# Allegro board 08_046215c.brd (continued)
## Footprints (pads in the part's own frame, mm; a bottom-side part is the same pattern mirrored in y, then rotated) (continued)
CNSMAL562W375H166
  rect 1.702x0.635 smd: 1(1.079,0)
  rect 5.08x2.54 smd: 2(-0.178,4.255) 3(-0.178,4.255) 4(-0.178,-4.255) 5(-0.178,-4.255)
CNTE2041517-1
  round 1.016 hole 0.711: 1(0,0) 2(1,0.8) 3(0,1.6) 4(1,2.4) 5(0,3.2)
  oval 1.219x2.413 hole 0.711x1.905: G1(-1.25,-0.3) G2(2.25,1.6)
  oval 1.219x2.616 hole 0.711x2.108: G3(-1.25,4)
DFN8_2X2_PAD1_5X1
  oval 0.305x0.61 smd: 1(-0.75,-1.05) 2(-0.25,-1.05) 3(0.25,-1.05) 4(0.75,-1.05) 5(0.75,1.05) 6(0.25,1.05) 7(-0.25,1.05) 8(-0.75,1.05)
  rect 1.499x0.991 smd: PAD(0,0)
DFN8_3X3_PAD2_38X1_64
  oval 0.305x0.838 smd: 1(-0.75,-1.45) 2(-0.25,-1.45) 3(0.25,-1.45) 4(0.75,-1.45) 5(0.75,1.45) 6(0.25,1.45) 7(-0.25,1.45) 8(-0.75,1.45)
  rect 2.388x1.651 smd: PAD(0,0)
DFN8_3X3_PAD2_44X1_6_A
  oval 0.305x0.838 smd: 1(-0.75,-1.45) 2(-0.25,-1.45) 3(0.25,-1.45) 4(0.75,-1.45) 5(0.75,1.45) 6(0.25,1.45) 7(-0.25,1.45) 8(-0.75,1.45)
  rect 2.438x1.6 smd: PAD(0,0)
DQFN16_3_5X2_5_PAD2_15X1_15
  oval 0.889x0.229 smd: 1(-1.795,-0.25) 8(1.795,-0.25) 9(1.795,0.25) 16(-1.795,0.25)
  oval 0.229x0.889 smd: 2(-1.25,-1.294) 3(-0.75,-1.294) 4(-0.25,-1.294) 5(0.25,-1.294) 6(0.75,-1.294) 7(1.25,-1.294) 10(1.25,1.294) 11(0.75,1.294) 12(0.25,1.294) 13(-0.25,1.294) 14(-0.75,1.294) 15(-1.25,1.294)
  rect 1.905x0.991 smd: PAD(0,0)
FLSML476W358H146
  rect 3.81x2.489 smd: 1(-6.845,2.1) 2(6.845,2.1) 3(-6.845,-2.1) 4(6.845,-2.1)
  rect 7.899x2.311 smd: 5(1,-5.094)
  rect 3.404x2.311 smd: 6(3.25,5.094)
HMC849LP4CE
  rect 0.33x0.889 smd: 1(-0.975,-1.841) 2(-0.325,-1.841) 3(0.325,-1.841) 4(0.975,-1.841) 9(0.975,1.841) 10(0.325,1.841) 11(-0.325,1.841) 12(-0.975,1.841)
  rect 0.889x0.33 smd: 5(1.841,-0.975) 6(1.841,-0.325) 7(1.841,0.325) 8(1.841,0.975) 13(-1.841,0.975) 14(-1.841,0.325) 15(-1.841,-0.325) 16(-1.841,-0.975)
  rect 2.388x2.388 smd: PAD(0,0)
L0302CS
  rect 0.254x0.533 smd: 1(-0.305,0) 2(0.305,0)
L0402
  rect 0.889x0.813 smd: 1(-0.635,0) 2(0.635,0)
L0402-2
  rect 0.381x0.66 smd: 1(-0.419,0) 2(0.419,0)
L0603
  rect 0.889x0.813 smd: 1(-0.737,0) 2(0.737,0)
L0603H28
  rect 1.041x0.991 smd: 1(-0.75,0) 2(0.75,0)
L1210
  rect 1.27x1.778 smd: 1(-1.397,0) 2(1.397,0)
LED0603
  rect 0.965x0.762 smd: A(0.8,0) C(-0.8,0)
LED0603H12
  rect 0.787x0.787 smd: A(0.744,0) C(-0.744,0)
LED0805
  rect 1.245x1.092 smd: A(1.172,0) C(-1.172,0)
LSML75W79H39
  rect 1.041x2.21 smd: 1(-0.724,0) 2(0.724,0)
LSML133W118H79
  rect 1.016x1.778 smd: 1(-0.889,0) 2(0.889,0)
LSMSQ130H55
  custom 0.311x0.311 smd: 1(-1.562,0) 2(1.562,0)
LSMSQ154H71
  custom 0.362x0.362 smd: 1(-1.847,0) 2(1.847,0)
LSMSQ157H83
  rect 1.473x3.683 smd: 1(-1.232,0) 2(1.232,0)
POWERPAKSC70-6
  rect 0.305x0.33 smd: 1(-0.65,-0.91) 2(0,-0.91) 3(0.65,-0.91) 4(0.65,0.91) 5(0,0.91) 6(-0.65,0.91)
  rect 0.61x0.94 smd: PAD1(-0.465,0) PAD2(0.465,0)
QFN16_3X3_PAD1_5X1_5
  oval 0.305x0.889 smd: 1(-0.75,-1.5) 2(-0.25,-1.5) 3(0.25,-1.5) 4(0.75,-1.5) 9(0.75,1.5) 10(0.25,1.5) 11(-0.25,1.5) 12(-0.75,1.5)
  oval 0.889x0.305 smd: 5(1.5,-0.75) 6(1.5,-0.25) 7(1.5,0.25) 8(1.5,0.75) 13(-1.5,0.75) 14(-1.5,0.25) 15(-1.5,-0.25) 16(-1.5,-0.75)
  rect 1.499x1.499 smd: PAD(0,0)
QFN16_3X3_PAD1_6X1_6
  oval 0.305x0.889 smd: 1(-0.75,-1.5) 2(-0.25,-1.5) 3(0.25,-1.5) 4(0.75,-1.5) 9(0.75,1.5) 10(0.25,1.5) 11(-0.25,1.5) 12(-0.75,1.5)
  oval 0.889x0.305 smd: 5(1.5,-0.75) 6(1.5,-0.25) 7(1.5,0.25) 8(1.5,0.75) 13(-1.5,0.75) 14(-1.5,0.25) 15(-1.5,-0.25) 16(-1.5,-0.75)
  rect 1.6x1.6 smd: PAD(0,0)
QFN24_4X4_PAD2_5X2_5
  oval 0.305x0.991 smd: 1(-1.25,-2) 2(-0.75,-2) 3(-0.25,-2) 4(0.25,-2) 5(0.75,-2) 6(1.25,-2) 13(1.25,2) 14(0.75,2) 15(0.25,2) 16(-0.25,2) 17(-0.75,2) 18(-1.25,2)
  oval 0.991x0.305 smd: 7(2,-1.25) 8(2,-0.75) 9(2,-0.25) 10(2,0.25) 11(2,0.75) 12(2,1.25) 19(-2,1.25) 20(-2,0.75) 21(-2,0.25) 22(-2,-0.25) 23(-2,-0.75) 24(-2,-1.25)
  rect 2.489x2.489 smd: PAD(0,0)
QFN28_6X6_PAD3_7X3_7
  oval 0.305x1.041 smd: 1(-1.95,-2.979) 2(-1.3,-2.979) 3(-0.65,-2.979) 4(0,-2.979) 5(0.65,-2.979) 6(1.3,-2.979) 7(1.95,-2.979) 15(1.95,2.979) 16(1.3,2.979) 17(0.65,2.979) 18(0,2.979) 19(-0.65,2.979) 20(-1.3,2.979) 21(-1.95,2.979)
  oval 1.041x0.305 smd: 8(2.979,-1.95) 9(2.979,-1.3) 10(2.979,-0.65) 11(2.979,0) 12(2.979,0.65) 13(2.979,1.3) 14(2.979,1.95) 22(-2.979,1.95) 23(-2.979,1.3) 24(-2.979,0.65) 25(-2.979,0) 26(-2.979,-0.65) 27(-2.979,-1.3) 28(-2.979,-1.95)
  rect 3.708x3.708 smd: PAD(0,0)
QFN32_5X5_PAD3_6X3_6
  oval 0.305x0.889 smd: 1(-1.75,-2.451) 2(-1.25,-2.451) 3(-0.75,-2.451) 4(-0.25,-2.451) 5(0.25,-2.451) 6(0.75,-2.451) 7(1.25,-2.451) 8(1.75,-2.451) 17(1.75,2.451) 18(1.25,2.451) 19(0.75,2.451) 20(0.25,2.451) 21(-0.25,2.451) 22(-0.75,2.451) 23(-1.25,2.451) 24(-1.75,2.451)
  oval 0.889x0.305 smd: 9(2.451,-1.75) 10(2.451,-1.25) 11(2.451,-0.75) 12(2.451,-0.25) 13(2.451,0.25) 14(2.451,0.75) 15(2.451,1.25) 16(2.451,1.75) 25(-2.451,1.75) 26(-2.451,1.25) 27(-2.451,0.75) 28(-2.451,0.25) 29(-2.451,-0.25) 30(-2.451,-0.75) 31(-2.451,-1.25) 32(-2.451,-1.75)
  rect 3.607x3.607 smd: PAD(0,0)
QFN38_7X5_PAD5_15X3_15
  oval 0.305x0.838 smd: 1(-2.75,-2.45) 2(-2.25,-2.45) 3(-1.75,-2.45) 4(-1.25,-2.45) 5(-0.75,-2.45) 6(-0.25,-2.45) 7(0.25,-2.45) 8(0.75,-2.45) 9(1.25,-2.45) 10(1.75,-2.45) 11(2.25,-2.45) 12(2.75,-2.45) 20(2.75,2.45) 21(2.25,2.45) 22(1.75,2.45) 23(1.25,2.45) 24(0.75,2.45) 25(0.25,2.45) 26(-0.25,2.45) 27(-0.75,2.45) 28(-1.25,2.45) 29(-1.75,2.45) 30(-2.25,2.45) 31(-2.75,2.45)
  oval 0.838x0.305 smd: 13(3.45,-1.5) 14(3.45,-1) 15(3.45,-0.5) 16(3.45,0) 17(3.45,0.5) 18(3.45,1) 19(3.45,1.5) 32(-3.45,1.5) 33(-3.45,1) 34(-3.45,0.5) 35(-3.45,0) 36(-3.45,-0.5) 37(-3.45,-1) 38(-3.45,-1.5)
  rect 5.156x3.15 smd: PAD(0,0)
QFN48_7X7_PAD5_6X5_6
  oval 0.305x0.94 smd: 1(-2.75,-3.5) 2(-2.25,-3.5) 3(-1.75,-3.5) 4(-1.25,-3.5) 5(-0.75,-3.5) 6(-0.25,-3.5) 7(0.25,-3.5) 8(0.75,-3.5) 9(1.25,-3.5) 10(1.75,-3.5) 11(2.25,-3.5) 12(2.75,-3.5) 25(2.75,3.5) 26(2.25,3.5) 27(1.75,3.5) 28(1.25,3.5) 29(0.75,3.5) 30(0.25,3.5) 31(-0.25,3.5) 32(-0.75,3.5) 33(-1.25,3.5) 34(-1.75,3.5) 35(-2.25,3.5) 36(-2.75,3.5)
  oval 0.94x0.305 smd: 13(3.5,-2.75) 14(3.5,-2.25) 15(3.5,-1.75) 16(3.5,-1.25) 17(3.5,-0.75) 18(3.5,-0.25) 19(3.5,0.25) 20(3.5,0.75) 21(3.5,1.25) 22(3.5,1.75) 23(3.5,2.25) 24(3.5,2.75) 37(-3.5,2.75) 38(-3.5,2.25) 39(-3.5,1.75) 40(-3.5,1.25) 41(-3.5,0.75) 42(-3.5,0.25) 43(-3.5,-0.25) 44(-3.5,-0.75) 45(-3.5,-1.25) 46(-3.5,-1.75) 47(-3.5,-2.25) 48(-3.5,-2.75)
  rect 5.588x5.588 smd: PAD(0,0)
R0201
  rect 0.305x0.406 smd: 1(-0.318,0) 2(0.318,0)
R0402
  rect 0.889x0.813 smd: 1(-0.635,0) 2(0.635,0)
R0603
  rect 1.092x1.194 smd: 1(-0.851,0) 2(0.851,0)
R1206
  rect 1.6x1.6 smd: 1(-1.397,0) 2(1.397,0)
SMB-4
  rect 2.489x2.311 smd: A(2.15,0) C(-2.15,0)
SO8NB-3-PAD
  rect 0.635x1.422 smd: 1(-1.905,-2.819) 2(-0.635,-2.819) 3(0.635,-2.819) 4(1.905,-2.819) 5(1.905,2.819) 6(0.635,2.819) 7(-0.635,2.819) 8(-1.905,2.819)
  rect 2.794x2.413 smd: PAD(0,0)
SOD123-3
  rect 1.194x0.711 smd: A(1.847,0) C(-1.847,0)
TPC65D45
  round 1.651 hole 1.143: 1(0,0)
TPSMC30
  round 0.762 smd: 1(0,0)
TSML150W160H160
  rect 0.762x1.651 smd: 1(-1.27,1.587) 2(0,1.587) 3(1.27,1.587) 4(1.27,-1.587) 5(0,-1.587) 6(-1.27,-1.587)
TSOT-5
  rect 0.508x1.524 smd: 1(-0.95,-1.17) 2(0,-1.17) 3(0.95,-1.17) 4(0.95,1.17) 5(-0.95,1.17)
TSSOP8
  rect 0.33x1.651 smd: 1(-0.975,-2.92) 2(-0.325,-2.92) 3(0.325,-2.92) 4(0.975,-2.92) 5(0.975,2.92) 6(0.325,2.92) 7(-0.325,2.92) 8(-0.975,2.92)
unnamed#2
  round 3.175 hole 2.667: 1(0,0)
YSML276W197H63
  rect 1.956x1.778 smd: 1(-2.54,-1.83) 2(0,-1.83) 3(2.54,-1.83) 4(2.54,1.83) 5(0,1.83) 6(-2.54,1.83)

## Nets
GND: C2.2(N2) C3.2(N2) C6.2(N2) C7.2(N2) C9.2(N2) C12.2(N2) C15.2(N2) C16.1 C17.1 C19.2(N2) C20.2(N2) C21.2(N2) C22.2(N2) C23.2(N2) C24.2(N2) C25.2(N2) C26.2(N2) C27.2(N2) C28.2(N2) C29.2(N2) C30.2(N2) C31.2(N2) C37.2(N2) C40.2(N2) C41.1 C42.1 C43.2(N2) C44.1 C45.1 C46.1 C47.1 C48.1 C49.1 C50.2(N2) C51.2(N2) C52.2(N2) C53.2(N2) C54.2(N2) C55.2(N2) C56.2(N2) C57.2(N2) C58.2(N2) C59.2(N2) C60.2(N2) C61.1 C63.1 C64.2(N2) C65.1 C66.1 C67.2(N2) C69.1 C71.2(N2) C72.2(N2) C76.2(N2) C77.2(N2) C310.1 C311.1 C312.1 C313.1 C314.2(N2) C315.1 C316.2(N2) C317.1 C323.1 C325.1 C326.2(N2) C327.2(N2) C328.2(N2) C330.2(N2) C331.2(N2) C338.1 C339.2(N2) C410.1 C411.1 C419.1 C420.1 C424.1 C426.2(N2) C427.1 C429.1 C430.1 C432.1 C433.2(N2) C435.2(N2) C436.2(N2) C437.2(N2) C443.1 C444.1 C446.1 C510.1 C513.1 C514.2(N2) C515.2(N2) C516.2(N2) C518.1 C522.1 C525.2(N2) C532.1 C535.1 C538.2(N2) C539.2(N2) C541.1 C544.2(N2) C545.2(N2) C546.1 C548.N(N2) C550.2(N2) C554.2(N2) C558.2(N2) C564.N(N2) C566.P C567.2(N2) C612.2(N2) C614.2(N2) C616.2(N2) C617.2(N2) C618.2(N2) C619.2(N2) C620.2(N2) C622.2(N2) C623.2(N2) C626.2(N2) C628.2(N2) C631.2(N2) C636.2(N2) C637.2(N2) C643.2(N2) C645.1 C648.2(N2) C649.1 C651.1 C654.2(N2) C655.2(N2) C656.1 C657.1 C658.1 C659.1 C660.1 C661.1 C662.1 C663.1 C664.1 C665.1 C666.1 C667.1 C668.1 C669.1 C670.1 C818.1 D1.A(P) FL1.3(PSG) FL1.4 FL1.5 FL1.6 J31.2 J31.3 J31.4 J31.5(SH4) J61.2 J61.3(SH2) J62.2 J62.3(SH2) L3.2(N2) L4.2(N2) L45.1 P1.A1 P1.A4 P1.A5 P1.A8 P1.A9 P1.A12 P1.A13 P1.A16 P1.A17 P1.A20 P1.A21 P1.A24 P1.A25 P1.A28 P1.A29 P1.A32 P1.A33 P1.A36 P1.A37 P1.A40 P1.B2 P1.B3 P1.B6 P1.B7 P1.B10 P1.B11 P1.B14 P1.B15 P1.B18 P1.B19 P1.B22 P1.B23 P1.B26 P1.B27 P1.B30 P1.B31 P1.B34 P1.B35 P1.B38 P1.B39 P1.C1 P1.C4 P1.C5 P1.C8 P1.C9 P1.C12 P1.C13 P1.C16 P1.C17 P1.C20 P1.C21 P1.C24 P1.C25 P1.C28 P1.C29 P1.C32 P1.C33 P1.C36 P1.C38 P1.C40 P1.D2 P1.D3 P1.D6 P1.D7 P1.D10 P1.D16 P1.D19 P1.D22 P1.D25 P1.D28 P1.D37 P1.D39 P1.E1 P1.E4 P1.E5 P1.E8 P1.E11 P1.E14 P1.E17 P1.E20 P1.E23 P1.E26 P1.E29 P1.E32 P1.E35 P1.E38 P1.E40 P1.F2 P1.F3 P1.F6 P1.F9 P1.F12 P1.F15 P1.F18 P1.F21 P1.F24 P1.F27 P1.F30 P1.F33 P1.F36 P1.F39 P1.G1 P1.G4 P1.G5 P1.G8 P1.G11 P1.G14 P1.G17 P1.G20 P1.G23 P1.G26 P1.G29 P1.G32 P1.G35 P1.G38 P1.G40 P1.H2 P1.H3 P1.H6 P1.H9 P1.H12 P1.H15 P1.H18 P1.H21 P1.H24 P1.H27 P1.H30 P1.H33 P1.H36 P1.H39 P1.J1 P1.J4 P1.J5 P1.J8 P1.J11 P1.J14 P1.J17 P1.J20 P1.J23 P1.J26 P1.J29 P1.J32 P1.J35 P1.J38 P1.J40 P1.K2 P1.K3 P1.K6 P1.K9 P1.K12 P1.K15 P1.K18 P1.K21 P1.K24 P1.K27 P1.K30 P1.K33 P1.K36 P1.K39 Q1.1 Q1.4(S2) Q2.1 Q2.4(S2) Q3.1 Q3.4(S2) Q4.1 Q4.4(S2) R1.2(N2) R3.2(N2) R8.1 R9.2(N2) R15.1 R17.2(N2) R27.2(N2) R41.1 R42.2(N2) R60.2(N2) R61.1 R67.2(N2) R69.1 R76.2(N2) R78.2(N2) R80.2(N2) R88.1 R310.1 R311.1 R328.1 R330.2(N2) R413.2(N2) R417.1 R423.2(N2) R424.2(N2) R429.1 R436.2(N2) R617.2(N2) R618.2(N2) R621.1 R623.2(N2) T33.2 TP42.1(N1) TP64.1(N1) U1.A13 U1.A14 U1.B1 U1.B2 U1.C2 U1.D2 U1.D3 U1.D13 U1.D14 U1.D15 U1.E1 U1.E2 U1.E3 U1.E13 U1.E14 U1.F6 U1.F7 U1.F8 U1.F9 U1.F10 U1.G2 U1.G3 U1.G8 U1.G13 U1.G14 U1.H1 U1.H3 U1.H6 U1.H7 U1.H8 U1.H9 U1.H10 U1.H13 U1.H15 U1.J6 U1.J7 U1.J8 U1.J9 U1.J10 U1.L1 U1.L2 U1.L14 U1.L15 U1.N6 U1.N7 U1.N10 U1.P1 U1.P15 U1.R2 U1.R5 U1.R8 U1.R11 U1.R14 U2.7 U2.PAD U3.7 U3.PAD U4.2 U5.5 U5.10 U5.11 U5.PAD U6.4 U6.PAD U7.PAD U8.9 U8.12 U8.13 U8.14 U8.24 U8.30 U8.PAD U9.8 U9.PAD U10.2 U10.3 U10.10 U10.11 U10.30 U10.PAD U11.10 U11.PAD U12.6 U13.4 U13.PAD U14.4 U14.PAD U15.8 U15.9 U15.13 U15.18 U15.21 U15.31 U15.PAD U16.7 U16.14 U16.PAD U17.4 U17.PAD U18.4 U18.PAD U19.4 U19.PAD U20.5 U20.16 U20.PAD U21.8 U21.10 U21.PAD U22.8 U22.PAD U23.4 U23.7(WC_N) XC4.N(N2) XC5.2(N2) XC6.2(N2) XC12.1 XP1.6(N6) XP2.5 XP2.G1 XP2.G2 XP2.G3(N8) Y61.3
SVDD12: C20.1 C26.1 C31.1 C37.1 C43.1 C52.1 C532.2(N2) C535.2(N2) C541.2(N2) C546.2(N2) C554.1 C567.1 U1.J2 U1.J14 U1.K2 U1.K14 U1.L3 U1.L13 U1.M2 U1.M3 U1.M13(VTT_1P2_2) U1.M14 U1.N2 U1.N8 U1.N9 U1.N14 U1.P3 U1.P4 U1.P6 U1.P7 U1.P9 U1.P10 U1.P12 U1.P13 U1.R1 U1.R15 U3.9 U3.10 U3.11 U3.12 U3.13
VCC: C58.1 R29.1 R30.1 R40.1 R50.2(N2) R51.2(N2) R52.2(N2) R53.1 R55.2(N2) R56.2(N2) R57.2(N2) R58.2(N2) R63.1 R68.1 R77.1 R79.1 R327.1 U8.22 U8.25(VSEL)
VDDA12: C50.1 C558.1 E9.1 U1.B13 U1.B14 U2.9 U2.10 U2.11 U2.12 U2.13
VDDA25: C1.2(N2) C5.2(N2) C32.2 C32.4 C32.6 C32.8(N8) C33.2 C33.4 C33.6 C33.8(N8) C35.2(N2) C36.2(N2) C513.2(N2) C531.1 C534.1 C537.1 C543.1 C549.1 E6.2(N2) E7.1 R33.1 R34.2(N2) R59.1 T1.3 U1.A2 U1.A5 U1.A6 U1.A9 U1.A10 U1.B3 U1.B6 U1.B7 U1.B8 U1.B9 U1.B12 U1.C4 U1.C7 U1.C8 U1.C11 U1.C15 U13.2
VDDA25_EN: Q4.3 Q4.PAD2 R52.1 U13.7
VDDC12: C526.P C533.1 C536.1 C539.1 C545.1 E9.2(N2) U1.E15 U1.F1 U1.F2 U1.F3 U1.F13 U1.F14 U1.F15
VIN_12V: C41.2(N2) C42.2(N2) C44.2(N2) C45.2(N2) C433.1 DS2.A(P) FL1.2 R54.1 R428.1 U10.6 U10.7 U10.22 U10.23 U10.24 U10.36 U10.37 U10.38 U11.12 U11.13
3P3VAUX: C818.2(N2) P1.D32 U23.8
73_SYNC: R429.2(N2) U11.4
73_VREF: C429.2(N2) R434.2(N2) U11.9
73_VREG: C430.2(N2) R425.1 U11.11(VREG)
AD9508_VDD: C323.2(N2) C327.1 C328.1 C330.1 C331.1 E32.1 R35.2(N2) R36.2(N2) R38.2(N2) R39.2(N2) R312.1 R313.1 U7.6 U7.13(VDD2)
ADCLK914OUT: C39.1 R625.1 U16.11
ADCLK914VCC: C654.1 C655.1 E68.2(N2) R622.1 R625.2(N2) U16.8 U16.13
ADF4355_VDD_3V3: C614.1 C616.1 C669.2(N2) JP1.2(S2) R611.2(N2) R619.2(N2) U15.5 U15.16 U15.27 U18.2
ADF4355_VRF_3V3: C623.1 C626.1 E5.1 E67.2(N2) L61.1 L62.2(N2) U15.10
ADF4355_VVCO_5V: C618.1 C619.1 C636.1 C643.1 C668.2(N2) U15.6 U15.17(VVCO) U15.19 U17.2
ADF4355OUTA: C632.2(N2) U16.2
ADF4355OUTAB: C633.2(N2) U16.1
ADF4355OUTB: C638.2(N2) U9.7
ADF4355OUTBB: C639.2(N2) U9.5
ADP5054_1V2: C2.1 C3.1 C16.2(N2) C17.2(N2) C18.1 C525.1 C538.1 C544.1 C550.1 C564.P E8.2(N2) R16.2(N2) U1.G6 U1.G7 U1.G9 U1.G10 U1.K6 U1.K7 U1.K8 U1.K9 U1.K10
ADP5054_1V5: C19.1 C28.1 C29.1 E1.2(N2) R2.2(N2) R24.1 R25.1 U2.1 U2.2 U2.3 U2.4 U2.16 U3.1 U3.2 U3.3 U3.4
ADP5054_3V8: C6.1 C56.1 C420.2(N2) C516.1 E2.2(N2) L1.1 L5.1 R63.2(N2) U4.1 U13.8 U14.8
ADP5054_5V5: C419.2(N2) E3.2(N2) E31.1 L2.1
ADP5073_2V2: C446.2(N2) E49.1 R443.1
CLK_N: C349.2(N2) U1.D1
CLK_P: C348.2(N2) U1.C1
CPOUT: C61.2(N2) C62.1 R62.1 U15.7
CS1: P2.2 R19.1 U20.20 U21.14
CS2: R38.1 R316.1 U20.10 U22.11
CS3: R615.1 U20.4 U22.13
DAC_CSB: R19.2(N2) U1.G15
DAC_SCLK: R23.2(N2) U1.J13
DAC_SDIO: R22.2(N2) U1.K13
DAC_SDO: R20.2(N2) U1.H14
DAC_TXEN_0: R8.2(N2) R18.2(N2) U1.H2
DIV2IN: C341.2(N2) U7.21
DIV2INB: C340.2(N2) U7.22
DL1: Q1.2 U10.31
DL2: Q1.5 U10.29
EN: Q3.3 Q3.PAD2 R51.1 U4.3
FMC_CS1: P1.H11 U21.3
FMC_CS2: P1.D11 U22.6
FMC_CS3: P1.D14 U22.4
FMC_HMC849VCTL: P1.D15 U22.3
FMC_MISO: P1.H10 U21.5
FMC_MOSI: P1.G10 U21.4
FMC_SCK: P1.G9 U21.6
FMC_SCL: P1.C30 U23.6
FMC_SDA: P1.C31 U23.5
FMC_SPI_EN: P1.D12 R72.2(N2) R73.2(N2) U20.6 U21.9 U22.9
FMC_TXEN_0: P1.H13 U22.5
FMCA_VCC_12P0V: C548.P D1.C FL1.1 P1.C35 P1.C37 TP41.1(N1)
GA0: P1.C34 U23.1
GA1: P1.D35 U23.2
GBTCLK0_M2C_N: C333.2(N2) P1.D5
GBTCLK0_M2C_P: C334.2(N2) P1.D4
HMC365_VDD: C317.2(N2) C338.2(N2) C339.1 U6.2 U9.4(VCC)
HMC365OUT: C341.1 R37.2(N2) R329.2(N2) U9.3
HMC365OUTB: C340.1 R37.1 R328.2(N2) U9.1
HMC849_VDD: C311.2(N2) C314.1 C316.1 E66.2(N2) U5.1(VDD)
HMC849VCTL: R31.2(N2) U20.9 U22.14
IRQB: CR5.C TP21.1(N1) U1.G1
LTC2928_ON: R70.2(N2) R416.1 U10.17
LTC2928_ON_A: R71.2(N2) U11.3
MISO: R20.1 U20.19 U21.12
MOSI: P2.1 R22.1 R36.1 R315.1 R614.1 U20.18 U21.13
OUT_N: E6.1 R33.2(N2) T1.6 U1.A7
OUT_P: E7.2(N2) R34.1 T1.4 U1.A8
PG_C2M: P1.D1 R47.2(N2) R410.2(N2) R411.2(N2) R412.2(N2) R428.2(N2) R436.1 U11.6
PGC: U20.24 XP1.3
PWRGD: DS1.C U8.19 U20.28
REF: R75.2(N2) U8.5
REF_4355_N: C610.1 Y61.5
REF_4355_P: C611.1 R65.1 Y61.4
SA_GND: C1.1 C5.1 C32.1 C32.3 C32.5 C32.7 C33.1 C33.3 C33.5 C33.7 C35.1 C36.1 J32.2 J32.3 J32.4 J32.5(SH4) L3.1 L4.1
SCK: P2.3(N3) R23.1 R35.1 R314.1 R613.1 U20.15 U21.11
SERDIN0_N: C816.1 U1.K15
SERDIN0_P: C815.1 U1.J15
SERDIN1_N: C82.1 U1.N15
SERDIN1_P: C81.1 U1.M15
SERDIN2_N: C84.1 U1.R12
SERDIN2_P: C83.1 U1.R13
SERDIN3_N: C86.1 U1.R9
SERDIN3_P: C85.1 U1.R10
SERDIN4_N: C811.1 U1.R7
SERDIN4_P: C812.1 U1.R6
SERDIN5_N: C87.1 U1.R4
SERDIN5_P: C88.1 U1.R3
SERDIN6_N: C813.1 U1.N1
SERDIN6_P: C814.1 U1.M1
SERDIN7_N: C89.1 U1.K1
SERDIN7_P: C810.1 U1.J1
SLEW: R425.2(N2) U11.2
SPI33: C59.1 E4.2(N2) R5.1 R6.1 U1.K3
SUPPLY33: C9.1 C76.1 C77.1 E4.1 E32.2(N2) R28.2(N2) R66.1 U4.5(VOUT) U20.11(VUSB) U20.17 U21.16(VCCB) U22.16(VCCB) XC4.P XC5.1 XC6.1 XP1.2 XR2.1 XR6.1
SVPLL12_EN: R338.2(N2) U3.16
SVSYN33_EN: R339.2(N2) U14.7
SVSYNC33: C522.2(N2) U1.P2 U1.P14 U14.2
SW1: C10.2(N2) L6.1 Q1.6 Q1.PAD1 U10.33 U10.34 U10.35
SW2: C412.2(N2) L7.1 Q1.3 Q1.PAD2 U10.25 U10.26 U10.27
SWITCH2BALUN: C38.1 R332.1
SYNC_N: JP34.1 R26.1 SYNCN.1(N1) U1.N11
SYNC_P: JP33.1 R26.2(N2) SYNCP.1(N1) U1.N12
SYSREF2_N: C344.2(N2) JP32.1
SYSREF2_P: C345.2(N2) JP31.1
SYSREF_N: C346.2(N2) R32.1 SYSRFN.1(N1) U1.N5
SYSREF_P: C347.2(N2) R32.2(N2) SYSRFP.1(N1) U1.N4
TOAD9508: R329.1 R629.2(N2)
TXEN_0: R18.1 U20.8 U22.12
UNNAMED_2_AD9162V4_I56_ISET: R7.1 U1.A15
UNNAMED_2_AD9162V4_I56_PLLLDOBY: R21.2(N2) U1.P8
UNNAMED_2_AD9162V4_I56_RESETN: R4.1 U1.J3
UNNAMED_2_AD9162V4_I56_VBGNEG: C8.1 U1.C12
UNNAMED_2_AD9162V4_I56_VREF: C23.1 U1.B15
UNNAMED_2_CAP_I33_N1: C21.1 R21.1
UNNAMED_2_CAP_I39_N1: C7.1 R3.1 R4.2(N2) R5.2(N2)
UNNAMED_2_DIOLED_I48_P: CR5.A(P) R6.2(N2)
UNNAMED_3_AD9508_I1155_EXTCAP1: C325.2(N2) U7.5
UNNAMED_3_AD9508_I1155_EXTCAP2: C326.1 U7.14
UNNAMED_3_AD9508_I1155_INSEL: R39.1 R330.1 U7.23
UNNAMED_3_AD9508_I1155_OUT0: C333.1 U7.2
UNNAMED_3_AD9508_I1155_OUT0B: C334.1 U7.3
UNNAMED_3_AD9508_I1155_OUT2: C344.1 U7.11
UNNAMED_3_AD9508_I1155_OUT2B: C345.1 U7.12
UNNAMED_3_AD9508_I1155_OUT3: C346.1 U7.16
UNNAMED_3_AD9508_I1155_OUT3B: C347.1 U7.17
UNNAMED_3_AD9508_I1155_RESETB: R311.2(N2) R312.2(N2) U7.18
UNNAMED_3_AD9508_I1155_S0: R314.2(N2) U7.19
UNNAMED_3_AD9508_I1155_S1: R315.2(N2) U7.24
UNNAMED_3_AD9508_I1155_S2: R316.2(N2) U7.1
UNNAMED_3_AD9508_I1155_SYNCB: R310.2(N2) R313.2(N2) U7.20
UNNAMED_3_ADM7150_I1277_BYP: C312.2(N2) U6.3
UNNAMED_3_ADM7150_I1277_EN: C313.2(N2) E31.2(N2) U6.7 U6.8
UNNAMED_3_ADM7150_I1277_REF: C315.2(N2) U6.5 U6.6
UNNAMED_3_ADM7150_I1277_VREG: C310.2(N2) U6.1(VREG)
UNNAMED_3_CAP_I1148_N2: C39.2(N2) U5.12
UNNAMED_3_CAP_I1149_N2: C34.2(N2) U5.9
UNNAMED_3_CAP_I1150_N2: C38.2(N2) U5.3
UNNAMED_3_CAP_I1305_N1: C349.1 T33.6(SEC_DOT)
UNNAMED_3_CAP_I1306_N1: C348.1 T33.4
UNNAMED_3_CAP_I1318_N1: C14.1 J32.1
UNNAMED_3_CAP_I1318_N2: C14.2(N2) T1.1 T1.2(NC1)
UNNAMED_3_CNBNC5P_I1037_CNTR: C34.1 J31.1
UNNAMED_3_ICHMC849LP4CE_I1139_V: R31.1 U5.2
UNNAMED_3_RES_I1265_N2: R332.2(N2) T33.3
UNNAMED_4_ADP5054_I1011_BST1: C10.1 U10.32
UNNAMED_4_ADP5054_I1011_BST2: C412.1 U10.28
UNNAMED_4_ADP5054_I1011_BST3: C413.1 U10.1
UNNAMED_4_ADP5054_I1011_BST4: C415.1 U10.12
UNNAMED_4_ADP5054_I1011_CFG12: R41.2(N2) R48.1 U10.18
UNNAMED_4_ADP5054_I1011_CFG34: R42.1 R49.1 U10.13
UNNAMED_4_ADP5054_I1011_COMP1: R44.2(N2) U10.40
UNNAMED_4_ADP5054_I1011_COMP2: R45.2(N2) U10.20
UNNAMED_4_ADP5054_I1011_COMP3: R46.2(N2) U10.47
UNNAMED_4_ADP5054_I1011_COMP4: R43.2(N2) U10.15
UNNAMED_4_ADP5054_I1011_EN1: R47.1 U10.39
UNNAMED_4_ADP5054_I1011_EN2: R410.1 U10.21
UNNAMED_4_ADP5054_I1011_EN3: R411.1 U10.48
UNNAMED_4_ADP5054_I1011_EN4: R412.1 U10.14
UNNAMED_4_ADP5054_I1011_FB1: C11.1 R15.2(N2) R16.1 U10.41
UNNAMED_4_ADP5054_I1011_FB2: C13.1 R1.1 R2.1 U10.19
UNNAMED_4_ADP5054_I1011_FB3: R420.2(N2) R424.1 U10.46
UNNAMED_4_ADP5054_I1011_FB4: R419.2(N2) R423.1 U10.16
UNNAMED_4_ADP5054_I1011_RT: R413.1 U10.42
UNNAMED_4_ADP5054_I1011_SW31: C413.2(N2) L44.1 U10.4 U10.5
UNNAMED_4_ADP5054_I1011_SW41: C415.2(N2) L42.1 U10.8 U10.9
UNNAMED_4_ADP5054_I1011_SYNC: R414.2(N2) U10.44
UNNAMED_4_ADP5054_I1011_VDD: C411.2(N2) U10.43
UNNAMED_4_ADP5073_I1002_COMP: C436.1 R437.1 U11.7
UNNAMED_4_ADP5073_I1002_FB: R430.2(N2) R434.1 U11.8
UNNAMED_4_ADP5073_I1002_SW: D42.C L45.2(N2) U11.1
UNNAMED_4_ADP7183_I808_VA: C434.2(N2) C435.1 U12.3
UNNAMED_4_ADP7183_I808_VAFB: C434.1 U12.4
UNNAMED_4_ADP7183_I808_VIN: C426.1 R443.2(N2) U12.8 U12.PAD
UNNAMED_4_ADP7183_I808_VREG: C427.2(N2) U12.7(VREG)
UNNAMED_4_CAP_I904_N2: C424.2(N2) D42.A(P) E49.2(N2) R430.1
UNNAMED_4_CAP_I948_N2: C443.2(N2) E2.1 L44.2(N2) R420.1
UNNAMED_4_CAP_I949_N2: C444.2(N2) E3.1 L42.2(N2) R419.1
UNNAMED_4_CAP_I1000_N1: C437.1 R437.2(N2)
UNNAMED_4_CAP_I1019_N2: C47.2(N2) R44.1
UNNAMED_4_CAP_I1026_N2: C48.2(N2) R45.1
UNNAMED_4_CAP_I1027_N2: C49.2(N2) R46.1
UNNAMED_4_CAP_I1028_N2: C46.2(N2) R43.1
UNNAMED_4_CAP_I1107_N2: C18.2(N2) R17.1
UNNAMED_4_CAP_I1125_N1: C11.2(N2) C12.1 C53.1 E8.1 L6.2(N2)
UNNAMED_4_CAP_I1127_N1: C13.2(N2) C15.1 C54.1 E1.1 L7.2(N2)
UNNAMED_4_DIOLED_I1138_N: DS2.C R417.2(N2)
UNNAMED_5_ADCLK914_I223_Q: C4.1 R622.2(N2) U16.12
UNNAMED_5_ADCLK914_I223_VREF: C649.2(N2) U16.15 U16.16
UNNAMED_5_ADF4355_I299_CE: R611.1 U15.4
UNNAMED_5_ADF4355_I299_CLK: R613.2(N2) U15.1
UNNAMED_5_ADF4355_I299_CREG2: C612.1 C617.1 U15.32
UNNAMED_5_ADF4355_I299_DATA: R614.2(N2) U15.2
UNNAMED_5_ADF4355_I299_LE: R615.2(N2) U15.3
UNNAMED_5_ADF4355_I299_MUXOUT: R620.1 U15.30
UNNAMED_5_ADF4355_I299_REFINA: C611.2(N2) R69.2(N2) R612.1 U15.29
UNNAMED_5_ADF4355_I299_REFINB: C610.2(N2) R612.2(N2) U15.28
UNNAMED_5_ADF4355_I299_RFOUTB: L64.1 R11.2(N2) R13.1 U15.15
UNNAMED_5_ADF4355_I299_RFOUTB_1: L63.2(N2) R11.1 R12.1 U15.14
UNNAMED_5_ADF4355_I299_RSET: R618.1 U15.22
UNNAMED_5_ADF4355_I299_VBIAS: C637.1 C645.2(N2) U15.24
UNNAMED_5_ADF4355_I299_VREF: C648.1 C651.2(N2) U15.23
UNNAMED_5_ADM7150_I186_BYP: C659.2(N2) U17.3
UNNAMED_5_ADM7150_I186_REF: C665.2(N2) U17.5 U17.6
UNNAMED_5_ADM7150_I186_VIN: C662.2(N2) L2.2(N2) U17.7 U17.8
UNNAMED_5_ADM7150_I186_VREG: C656.2(N2) U17.1(VREG)
UNNAMED_5_ADM7154_I181_BYP: C661.2(N2) U19.3
UNNAMED_5_ADM7154_I181_REF: C667.2(N2) U19.5 U19.6
UNNAMED_5_ADM7154_I181_VIN: C664.2(N2) L1.2(N2) U19.7 U19.8
UNNAMED_5_ADM7154_I181_VOUT: C670.2(N2) R626.1 R627.1 R628.1 U19.2
UNNAMED_5_ADM7154_I181_VREG: C658.2(N2) U19.1(VREG)
UNNAMED_5_ADM7154_I297_BYP: C660.2(N2) U18.3
UNNAMED_5_ADM7154_I297_EN: C663.2(N2) L5.2(N2) U18.7 U18.8
UNNAMED_5_ADM7154_I297_REF: C666.2(N2) U18.5 U18.6
UNNAMED_5_ADM7154_I297_VREG: C657.2(N2) U18.1(VREG)
UNNAMED_5_CAP_I32_N2: C66.2(N2) R62.2(N2) R64.1
UNNAMED_5_CAP_I90_N1: C633.1 L62.1 U15.12
UNNAMED_5_CAP_I203_N2: C63.2(N2) C65.2(N2) JP1.1 Y61.6(VDD)
UNNAMED_5_CAP_I269_N1: C620.1 C622.1 U15.25
UNNAMED_5_CAP_I292_N1: C638.1 R12.2(N2) R14.1
UNNAMED_5_CAP_I293_N1: C639.1 R13.2(N2) R14.2(N2)
UNNAMED_5_CAP_I294_N1: C632.1 L61.2(N2) U15.11
UNNAMED_5_CAP_I329_N1: C628.1 C631.1 E5.2(N2) L63.1 L64.2(N2)
UNNAMED_5_CAP_I349_N2: C62.2(N2) R61.2(N2)
UNNAMED_5_CNBNC3P_I279_CNTR: C4.2(N2) J62.1 R623.1
UNNAMED_5_CNBNC3P_I308_CNTR: J61.1 R65.2(N2) R629.1
UNNAMED_5_DIOLED_I73_N: DS61.C R621.2(N2)
UNNAMED_5_DIOLED_I73_P: DS61.A(P) R620.2(N2)
UNNAMED_5_FERRITE_I346_N1: E68.1 R626.2(N2)
UNNAMED_5_FERRITE_I347_N1: E67.1 R628.2(N2)
UNNAMED_5_FERRITE_I348_N1: E66.1 R627.2(N2)
UNNAMED_5_RES_I49_N1: R617.1 R619.1 U15.26
UNNAMED_6_CAP_I116_N2: U20.3 XC12.2(N2)
UNNAMED_6_CN6P_I38_N1: U20.25 XP1.1
UNNAMED_6_CN6P_I38_N5: U20.26 XP1.5 XR2.2(N2)
UNNAMED_6_DIOLED_I258_N: U20.21 XCR1.C
UNNAMED_6_DIOLED_I258_P: XCR1.A(P) XR6.2(N2)
UNNAMED_6_ICPIC18F2XJ50_I109_OS: R28.1 U20.7
UNNAMED_6_ICPIC18F2XJ50_I109_RC: R10.1 U20.14
UNNAMED_7_CAP_I162_N2: C811.2(N2) P1.B32
UNNAMED_7_CAP_I163_N2: C812.2(N2) P1.B33
UNNAMED_7_CAP_I164_N2: C813.2(N2) P1.B36
UNNAMED_7_CAP_I165_N2: C814.2(N2) P1.B37
UNNAMED_7_CAP_I166_N2: C82.2(N2) P1.A23
UNNAMED_7_CAP_I167_N2: C81.2(N2) P1.A22
UNNAMED_7_CAP_I168_N2: C84.2(N2) P1.A27
UNNAMED_7_CAP_I169_N2: C83.2(N2) P1.A26
UNNAMED_7_CAP_I170_N2: C86.2(N2) P1.A31
UNNAMED_7_CAP_I171_N2: C85.2(N2) P1.A30
UNNAMED_7_CAP_I172_N2: C88.2(N2) P1.A35
UNNAMED_7_CAP_I173_N2: C87.2(N2) P1.A34
UNNAMED_7_CAP_I174_N2: C810.2(N2) P1.A39
UNNAMED_7_CAP_I175_N2: C89.2(N2) P1.A38
UNNAMED_7_CAP_I176_N2: C816.2(N2) P1.C3
UNNAMED_7_CAP_I177_N2: C815.2(N2) P1.C2
UNNAMED_7_CN400PAKV2_I143_LA01N: JP34.2(N2) P1.D9
UNNAMED_7_CN400PAKV2_I143_LA01P: JP33.2(N2) P1.D8
UNNAMED_7_CN400PAKV2_I143_TDI: P1.D30 P1.D31
UNNAMED_7_CN400PAKV2_I147_LA02N: JP32.2(N2) P1.H8
UNNAMED_7_CN400PAKV2_I147_LA02P: JP31.2(N2) P1.H7
UNNAMED_7_ICM24CXX_I210_E2: R88.2(N2) U23.3
UNNAMED_9_ADM7154_I249_BYP: C515.1 U14.3
UNNAMED_9_ADM7154_I249_REF: C518.2(N2) U14.5 U14.6
UNNAMED_9_ADM7154_I249_VREG: C514.1 U14.1(VREG)
UNNAMED_9_ADM7154_I278_BYP: C55.1 U13.3
UNNAMED_9_ADM7154_I278_REF: C510.2(N2) U13.5 U13.6
UNNAMED_9_ADM7154_I278_VREG: C51.1 U13.1(VREG)
UNNAMED_9_ADP176X_I287_PG: R24.2(N2) U2.15
UNNAMED_9_ADP176X_I287_REFCAP: C25.1 U2.5
UNNAMED_9_ADP176X_I287_SS: C22.1 U2.14
UNNAMED_9_ADP176X_I287_VREG: C30.1 U2.6(VREG)
UNNAMED_9_ADP176X_I303_PG: R25.2(N2) U3.15
UNNAMED_9_ADP176X_I303_REFCAP: C27.1 U3.5
UNNAMED_9_ADP176X_I303_SS: C24.1 U3.14
UNNAMED_9_ADP176X_I303_VREG: C40.1 U3.6(VREG)
UNNAMED_9_CAPP_I31_N2: C526.N(N2) R27.1
UNNAMED_10_CAP_I3_N1: C64.1 U8.26
UNNAMED_10_CAP_I4_N1: C60.1 U8.27
UNNAMED_10_CAP_I5_N1: C67.1 U8.28
UNNAMED_10_CAP_I7_N1: C57.1 R54.2(N2) U8.23
UNNAMED_10_DIOLED_I29_P: DS1.A(P) R327.2(N2)
UNNAMED_10_LINLTC2928_I1_DONEN: R53.2(N2) U8.18
UNNAMED_10_LINLTC2928_I1_EN1: Q2.2 U8.2
UNNAMED_10_LINLTC2928_I1_EN2: Q3.2 U8.37
UNNAMED_10_LINLTC2928_I1_EN3: Q4.2 U8.31
UNNAMED_10_LINLTC2928_I1_ON: R68.2(N2) R70.1 R71.1 U8.16
UNNAMED_10_LINLTC2928_I1_OVA: R55.1 R76.1 U8.1
UNNAMED_10_LINLTC2928_I1_RT1: R56.1 U8.6
UNNAMED_10_LINLTC2928_I1_RT2: R58.1 U8.7
UNNAMED_10_LINLTC2928_I1_RT3: R57.1 U8.8
UNNAMED_10_LINLTC2928_I1_SQT1: R77.2(N2) R78.1 U8.10
UNNAMED_10_LINLTC2928_I1_SQT2: R79.2(N2) R80.1 U8.11
UNNAMED_10_LINLTC2928_I1_V1: R74.2(N2) R75.1 U8.3
UNNAMED_10_LINLTC2928_I1_V2: R66.2(N2) R67.1 U8.38
UNNAMED_10_LINLTC2928_I1_V3: R59.2(N2) R60.1 U8.32
UNNAMED_10_RES_I26_N1: Q2.3 Q2.PAD2 R50.1 R337.1 R338.1 R339.1
UNNAMED_10_TRANNMOSFET2PAD_I17_: Q4.5 Q4.6 Q4.PAD1 R29.2(N2)
UNNAMED_10_TRANNMOSFET2PAD_I21_: Q3.5 Q3.6 Q3.PAD1 R40.2(N2)
UNNAMED_10_TRANNMOSFET2PAD_I24_: Q2.5 Q2.6 Q2.PAD1 R30.2(N2)
USB_D+: U20.13 XP2.3
USB_D-: U20.12 XP2.2
USB_VCC: R9.1 R10.2(N2) XP2.1
VADJ: C71.1 C72.1 P1.E39 P1.F40 P1.G39 P1.H40 P1.J39 P1.K40 R72.1 R73.1 U21.1 U21.2 U21.7 U21.15 U22.1 U22.2 U22.7 U22.10 U22.15
VNEG12: C8.2(N2) C531.2(N2) C533.2(N2) C534.2(N2) C536.2(N2) C537.2(N2) C543.2(N2) C549.2(N2) C566.N(N2) R7.2(N2) R445.2(N2) TP43.1(N1) U1.A1 U1.A3 U1.A4 U1.A11 U1.A12 U1.B4 U1.B5 U1.B10 U1.B11 U1.C5 U1.C6 U1.C9 U1.C10 U1.C14
VNEG12_EN: R337.2(N2) U12.5
VOUT: C432.2(N2) R74.1 R445.1 U12.1 U12.2
VREG: C410.2(N2) R48.2(N2) R49.2(N2) R414.1 R416.2(N2) U10.45(VREG)
VTUNE: C69.2(N2) R64.2(N2) U15.20

Pads without a net: NOREF#23 1; NOREF#25 1; P1 A2 A3 A6 A7 A10 A11 A14 A15 A18 A19 B1 B4 B5 B8 B9 B12 B13 B16 B17 B20 B21 B24 B25 B28 B29 B40 C6 C7 C10 C11 C14 C15 C18 C19 C22 C23 C26 C27 C39 D13 D17 D18 D20 D21 D23 D24 D26 D27 D29 D33 D34 D36 D38 D40 E2 E3 E6 E7 E9 E10 E12 E13 E15 E16 E18 E19 E21 E22 E24 E25 E27 E28 E30 E31 E33 E34 E36 E37 F1 F4 F5 F7 F8 F10 F11 F13 F14 F16 F17 F19 F20 F22 F23 F25 F26 F28 F29 F31 F32 F34 F35 F37 F38 G2 G3 G6 G7 G12 G13 G15 G16 G18 G19 G21 G22 G24 G25 G27 G28 G30 G31 G33 G34 G36 G37 H1 H4 H5 H14 H16 H17 H19 H20 H22 H23 H25 H26 H28 H29 H31 H32 H34 H35 H37 H38 J2 J3 J6 J7 J9 J10 J12 J13 J15 J16 J18 J19 J21 J22 J24 J25 J27 J28 J30 J31 J33 J34 J36 J37 K1 K4 K5 K7 K8 K10 K11 K13 K14 K16 K17 K19 K20 K22 K23 K25 K26 K28 K29 K31 K32 K34 K35 K37 K38; T33 1 5; U1 P5 P11; U2 8; U3 8; U4 4; U5 4 6 7 8 13 14 15 16; U7 4 7 8 9 10 15; U8 4 15 17 20 21 29 33 34 35 36; U9 2 6; U11 5 14 15 16; U16 3 4 5 6 9 10; U20 1 2 22 23 27; XP1 4; XP2 4; Y61 1 2

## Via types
v1: diameter 0.508, hole 0.254, TOP to BOTTOM, 342 vias
v2: diameter 0.508, hole 0.254, L2_GROUND to L11_GROUND, 10 vias
v3: diameter 0.381, hole 0.203, L11_GROUND to BOTTOM, 67 vias
v4: diameter 0.635, hole 0.305, TOP to BOTTOM, 349 vias
v5: diameter 0.381, hole 0.203, TOP to L2_GROUND, 133 vias
v6: diameter 0.254, hole 0.127, TOP to BOTTOM, 141 vias

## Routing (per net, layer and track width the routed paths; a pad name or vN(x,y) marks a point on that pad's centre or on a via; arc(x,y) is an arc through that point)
GND: length 577.4
  TOP w0.254: U15.21 24.76,11.65 v5(24.51,11.9) ; v1(17.65,24.98) 18.63,25.95 U5.5 ; v4(44.96,4.53) 45.21,4.79 R310.1 ; U15.31 25.76,13.15 v5(24.51,11.9) ; v5(24.51,11.9) v5(23.24,13.17) 22.76,13.65 ; v5(24.51,11.9) 24.26,11.65 ; U1.G3 U1.G2 ; U1.G3 U1.H3 ; U1.G3 v6(28.33,37.54) ; U1.R5 v6(33.4,38.08) ; v4(56.13,47.97) 56.79,47.31 U21.10 ; C339.2 v5(34.92,6.82) ; Q3.4 v5(11.51,65.03) ; 14.99,18.12 15.49,18.63 U16.7 ; U21.8 59.43,46.31 U21.PAD ; R618.2 v5(24.64,6.69) ; U1.R11 v6(32.87,41.08) ; 24.26,11.65 U15.13 ; 24.26,11.65 23.26,10.65 U15.18 ; U5.11 15.18,24.65 v5(14.99,24.85) ; Q3.1 9.52,63.21 9.14,63.59 v5(9.14,63.84) ; Q2.4 v5(7.32,65.03) ; Q4.1 v5(13.34,63.21) ; C637.2 v5(26.86,7.52) ; U1.D14 v6(26.83,42.08) ; U1.D14 U1.D15 ; U1.D14 v6(27.33,42.58) U1.E13 ; v5(14.73,18.38) 14.48,18.63 U16.14 ; C328.2 C327.2 43.88,13.36 v4(43.69,13.55) ; 22.76,13.65 U15.8 ; 22.76,13.65 U15.9 ; Q4.4 v5(15.45,65.03) ; U18.4 11.82,10.11 v5(12.57,9.36) ; Q2.1 v5(5.21,63.21) ; v5(38.61,8.85) 39.36,8.1 U17.4 ; U3.7 30.74,56.73 v5(30.99,56.98) ; U1.D2 v6(26.83,37.08) U1.E3 U1.E2 ; U1.D2 U1.C2 v6(25.83,36.58) v6(25.83,36.08) ; U1.D2 U1.E2 ; C311.1 v5(21.84,21.93) ; v6(30.33,43.5) U1.L15 U1.L14 ; U22.8 66.8,42.5 v5(66.55,42.25) ; v5(21.97,57.49) v5(21.46,56.98) 21.21,56.73 U2.7 ; v6(31.83,43.08) v6(31.83,43.47) ; U1.F10 v5(27.83,40.08) v5(27.83,39.58) ; v6(28.33,39.58) v5(27.83,39.58) ; v5(27.83,39.58) v5(27.83,39.08) U1.F6 ; R311.1 v4(42.29,7.07) ; v6(31.33,38.58) v6(31.33,39.08) ; v6(28.83,38.58) v6(28.83,39.08) v6(28.83,39.58) v6(28.83,40.08) v6(28.83,40.58) v6(28.83,40.98) ; U1.H1 v6(28.83,35.52) ; v6(29.33,40.58) v6(29.33,40.08) v6(29.33,39.58) v6(29.33,39.08) v6(29.33,38.58) ; U1.H13 v5(28.33,42.08) U1.G14 ; v6(28.83,43.08) v6(28.83,43.52) ; C314.2 v5(20.95,21.93) ; U1.R8 v6(32.89,39.58) ; U1.R2 v6(32.84,36.58) ; U1.E2 v6(27.33,36.08) ; U1.R14 v6(32.81,42.58) ; U5.10 v5(15.04,25.3) ; C654.2 v1(18.22,19.58) ; U1.L2 v6(30.33,36.08)
  TOP w0.305: C636.2 v5(22.54,7.39) C643.2 ; v5(21.4,16.66) C619.2 C618.2 ; v5(72.64,57.24) 72.46,57.05 U23.7 ; v4(51.37,13.49) C330.2 C331.2 ; v1(26.99,32.52) 26.99,32.98 ; v5(9.78,57.87) 10.53,57.12 U13.4 ; U23.4 v4(71.16,62.66) ; U20.16 50.26,58.99 U20.PAD 50.91,60.94 U20.5 ; R88.1 v4(71.12,64.86) ; C56.2 6.73,57.31 v4(5.77,56.35) ; 26.1,32.98 v1(26.1,32.52) ; v1(20.37,25.93) 20.95,25.93 ; C655.2 v4(10.67,19.14) ; R328.1 v4(49.15,2.37) ; 10.41,21.61 v4(10.41,21.93)
  TOP w0.33: R623.2 9.59,21.61 v1(9.27,21.93)
  TOP w0.508: v5(12.57,9.36) v5(13.34,9.36) ; C669.1 v4(11.86,14.91) ; v4(3.81,27.77) 3.81,28.41 3.3,28.92 L4.2 ; C660.1 v4(10.29,12.28) ; v5(9.27,50.89) 9.91,51.52 C513.1 ; C72.2 61.96,41.49 v1(61.26,40.78) ; C510.1 v5(15.86,61.61) ; D1.A v4(57.9,3.4) ; v4(36.2,2.63) 36.07,2.75 C656.1 ; C326.2 42.72,12.86 v4(42.67,12.91) ; U4.2 v4(33.66,64.6) ; J62.2 U19.PAD ; J62.2 v4(2.15,7.06) ; J62.2 v4(2.15,15.59) ; C51.2 v5(7.75,50.89) ; C665.1 v4(41.15,12.15) ; v4(59.18,45.43) U21.PAD ; v4(12.61,4.32) C663.1 13.34,4.32 ; C429.1 52.45,48.35 v1(52.45,48.73) ; C52.2 28.87,54.41 v4(28.57,54.7) 28.07,55.21 C40.2 ; R69.1 v4(29.59,14.69) ; v4(36.32,21.55) 36.88,22.11 Y61.3 ; C27.2 26.45,58.55 25.91,58 v4(25.91,57.36) 25.91,56.6 ; 35.81,56.35 36.23,56.77 v4(36.23,57.4) ; T33.2 v4(26.58,25.02) ; J62.3 7.76,15.09 v4(7.44,15.4) ; C7.2 30.99,24.6 v4(30.61,24.98) ; L3.2 2.29,49.62 1.91,50 v5(1.91,50.63) ; L3.2 v5(2.79,50.76) ; L3.2 3.3,49.62 3.81,50.13 v5(3.81,50.63) ; v5(37.08,8.47) 36.28,9.27 C662.1 ; R27.2 v4(18.03,51.4) ; v4(25.27,2.5) U9.8 26.66,2.5 ; C21.2 v4(34.29,44.54) ; R617.2 30.1,8.85 v5(30.61,8.85) ; v4(59.31,3.26) C548.N v4(60.71,2.12) ; C325.1 v4(52.67,11.3) ; R330.2 v4(49.78,4.41) ; v4(59.56,37.81) 59.44,37.81 59.18,38.06 R17.2 ; J61.2 v4(29.2,22.55) ; R3.2 v4(35.81,25.87) ; L4.2 2.29,28.92 1.91,28.54 v4(1.91,27.77) ; L4.2 v4(2.79,27.77) ; v4(26.92,47.46) 26.42,46.95 C23.2 ; C316.2 v4(25.78,22.82) ; J61.3 v4(34.81,16.23) ; v4(37.63,54.61) 37.14,54.11 37.14,52.61 C567.2 v4(38.61,52.54) ; 75.18,59.78 v4(74.68,59.78) ; v5(14.73,18.38) 14.99,18.12 ; 44.83,22.06 45.09,21.8 C65.1 46.06,21.26 46.1,21.3 46.61,20.79 C63.1 ; C649.1 v4(11.18,16.47) ; 66.29,47.08 v5(66.29,47.59) ; v4(9.78,7.33) 9.78,6.56 C666.1 ; R8.1 v4(35.67,35.5) ; 33.53,10.34 v5(33.53,11.14) ; v4(29.21,66.51) 30.14,65.58 C9.2 ; C659.1 v5(40.42,8.85) ; R417.1 v4(51.31,2.37) ; 17.4,4.79 v4(17.4,3.9) ; R621.1 v4(26.04,21.17) ; v4(57.28,41.11) 56.39,42 C76.2 ; C55.2 12.83,58.25 v4(12.07,59.02) ; C29.2 v4(28,60.29) ; C30.2 v4(16.29,55.88) ; C668.1 v4(38.35,3.14)
  TOP w0.635: XP1.6 62.45,65.53 ; XP1.6 60.74,65.53 ; XP1.6 62.45,67.23 ; XP1.6 60.74,67.23 ; 45.17,63.11 XP2.G1 47,63.11 ; TP64.1 72.56,4.07 ; TP64.1 70.95,2.46 ; TP64.1 70.95,4.07 ; TP64.1 72.56,2.46 ; 18.53,19.63 TP42.1 ; TP42.1 20.59,21.69 ; TP42.1 18.53,21.69
  L2_GROUND w0.508: 46.1,55.59 46.08,55.61 XP2.G3 ; 46.1,63.33 46.08,63.31 XP2.G1
  L2_GROUND w0.635: 45.17,63.11 XP2.G1 47,63.11 ; 70.95,4.07 TP64.1 ; TP64.1 70.95,2.46 ; TP64.1 72.56,2.46 ; TP64.1 72.56,4.07 ; 44.21,57.48 XP2.5 45.46,58.73 ; TP42.1 20.59,19.63 ; TP42.1 18.53,19.63 ; TP42.1 18.53,21.69 ; TP42.1 20.59,21.69 ; XP1.6 62.45,67.23 ; XP1.6 62.45,65.53 ; XP1.6 60.74,65.53 ; XP1.6 60.74,67.23 ; 41.67,61.21 XP2.G2 41.67,58.19 ; 45.17,55.69 XP2.G3 ; XP2.G3 47,55.69 ; XP2.G3 47,58.91
  L3_SIGNAL w0.635: 41.67,58.19 XP2.G2 41.67,61.21 ; TP64.1 72.56,2.46 ; TP64.1 72.56,4.07 ; TP64.1 70.95,4.07 ; TP64.1 70.95,2.46 ; 45.17,63.11 XP2.G1 47,63.11 ; 44.21,57.48 XP2.5 45.46,58.73 ; 60.74,65.53 XP1.6 ; XP1.6 60.74,67.23 ; XP1.6 62.45,65.53 ; XP1.6 62.45,67.23 ; TP42.1 20.59,19.63 ; TP42.1 18.53,19.63 ; TP42.1 20.59,21.69 ; TP42.1 18.53,21.69
  L4_GROUND w0.635: 60.74,65.53 XP1.6 ; XP1.6 62.45,65.53 ; XP1.6 60.74,67.23 ; XP1.6 62.45,67.23 ; TP42.1 20.59,21.69 ; TP42.1 18.53,19.63 ; TP42.1 20.59,19.63 ; TP42.1 18.53,21.69 ; 70.95,4.07 TP64.1 ; TP64.1 70.95,2.46 ; TP64.1 72.56,4.07 ; TP64.1 72.56,2.46 ; XP2.G3 47,55.69 ; XP2.G3 47,58.91 ; XP2.G3 45.17,55.69 ; 45.46,58.73 XP2.5 44.21,57.48 ; 47,63.11 XP2.G1 45.17,63.11 ; 41.67,61.21 XP2.G2 41.67,58.19
  L6_POWER w0.508: v4(34.16,61.68) 34.16,61.07 33.96,60.87
  L6_POWER w0.635: TP42.1 20.59,21.69 ; TP42.1 18.53,21.69 ; TP42.1 20.59,19.63 ; TP42.1 18.53,19.63
  L7_GROUND w0.635: 45.46,58.73 XP2.5 44.21,57.48 ; 60.74,65.53 XP1.6 ; XP1.6 60.74,67.23 ; XP1.6 62.45,67.23 ; XP1.6 62.45,65.53 ; 18.53,21.69 TP42.1 ; TP42.1 18.53,19.63 ; TP42.1 20.59,21.69 ; TP42.1 20.59,19.63 ; TP64.1 72.56,4.07 ; TP64.1 70.95,2.46 ; TP64.1 70.95,4.07 ; TP64.1 72.56,2.46 ; XP2.G3 47,58.91 ; XP2.G3 47,55.69 ; XP2.G3 45.17,55.69 ; 47,63.11 XP2.G1 45.17,63.11 ; 41.67,61.21 XP2.G2 41.67,58.19
  L9_GROUND w0.635: TP64.1 72.56,4.07 ; TP64.1 70.95,4.07 ; TP64.1 70.95,2.46 ; TP64.1 72.56,2.46 ; 60.74,65.53 XP1.6 ; XP1.6 62.45,67.23 ; XP1.6 60.74,67.23 ; XP1.6 62.45,65.53 ; 44.21,57.48 XP2.5 45.46,58.73 ; 47,63.11 XP2.G1 45.17,63.11 ; 41.67,61.21 XP2.G2 41.67,58.19 ; TP42.1 20.59,19.63 ; TP42.1 18.53,19.63 ; TP42.1 18.53,21.69 ; TP42.1 20.59,21.69 ; XP2.G3 47,55.69 ; XP2.G3 47,58.91 ; XP2.G3 45.17,55.69
  L10_SIGNAL w0.635: XP1.6 62.45,65.53 ; XP1.6 62.45,67.23 ; XP1.6 60.74,67.23 ; XP1.6 60.74,65.53 ; 18.53,21.69 TP42.1 20.59,21.69 ; 45.46,58.73 XP2.5 44.21,57.48 ; TP64.1 72.56,4.07 ; TP64.1 70.95,2.46 ; TP64.1 72.56,2.46 ; TP64.1 70.95,4.07 ; 41.67,58.19 XP2.G2 41.67,61.21 ; XP2.G3 47,55.69 ; XP2.G3 47,58.91 ; XP2.G3 45.17,55.69
  L11_GROUND w0.635: 60.74,65.53 XP1.6 ; XP1.6 62.45,65.53 ; XP1.6 62.45,67.23 ; XP1.6 60.74,67.23 ; 18.53,21.69 TP42.1 ; TP42.1 18.53,19.63 ; TP42.1 20.59,19.63 ; TP42.1 20.59,21.69 ; 70.95,2.46 TP64.1 ; TP64.1 72.56,2.46 ; TP64.1 72.56,4.07 ; TP64.1 70.95,4.07 ; 41.67,58.19 XP2.G2 41.67,61.21 ; 45.17,63.11 XP2.G1 47,63.11 ; XP2.G3 47,55.69 ; XP2.G3 47,58.91 ; XP2.G3 45.17,55.69 ; 45.46,58.73 XP2.5 44.21,57.48
  BOTTOM w0.254: P1.J1 v1(62.53,58.56) ; P1.F21 v1(66.34,33.16) ; P1.F6 v1(66.34,52.21) ; P1.B19 v1(71.42,35.7) ; P1.E29 v1(67.61,23) ; P1.H9 v1(63.8,48.4) ; P1.H24 v1(63.8,29.35) ; v6(30.33,36.08) 30.35,36.06 30.35,35.77 30.54,35.58 C26.2 ; P1.E40 v1(67.61,9.03) ; P1.K18 v1(62.53,38.24) P1.J17 ; P1.K24 v1(61.26,29.35) ; 44.73,27.93 44.23,27.43 U10.11 ; 44.73,27.93 45.59,28.79 ; 44.73,27.93 U10.10 ; P1.C20 v1(70.15,34.43) ; P1.H21 v1(63.8,33.16) ; P1.D7 v1(68.88,50.94) ; U14.4 36.71,61.69 v4(37.47,62.44) ; P1.H6 v1(63.8,52.21) ; P1.K15 v1(61.26,40.78) ; P1.B15 v1(71.42,40.78) ; v3(29.84,8.85) 29.09,8.1 U6.4 ; P1.A25 v1(72.69,28.08) ; P1.G1 v1(65.07,58.56) ; P1.G29 v1(65.07,23) ; P1.G4 v1(65.07,54.75) ; P1.G40 v1(65.07,9.03) ; P1.D28 v1(68.88,24.27) ; P1.E5 v1(67.61,53.48) ; P1.K9 v1(61.26,48.4) ; P1.A9 v1(72.69,48.4) ; P1.B18 v1(71.42,36.97) ; P1.E1 v1(67.61,58.56) ; P1.A17 v1(72.69,38.24) ; P1.B14 v1(71.42,42.05) ; P1.J29 v1(62.53,23) ; v3(53.34,46.32) 53.59,46.57 U11.10 ; P1.E20 v1(67.61,34.43) ; P1.C21 v1(70.15,33.16) ; P1.K6 v1(61.26,52.21) ; P1.D6 v1(68.88,52.21) ; U8.9 8.61,56.37 U8.PAD ; P1.A8 v1(72.69,49.67) ; v4(12.07,59.02) 12.11,59.06 U8.30 ; Q1.1 v4(47.27,35.88) ; P1.D19 v1(68.88,35.7) ; P1.F24 v1(66.34,29.35) ; Q1.4 45.58,37.95 v4(45.34,38.19) ; P1.A21 v1(72.69,33.16) ; P1.A24 v1(72.69,29.35) ; P1.G20 v1(65.07,34.43) ; P1.K21 v1(62.53,34.43) P1.J20 ; U12.6 v3(19.94,60.16) ; P1.F9 v1(66.34,48.4) ; P1.B7 v1(71.42,50.94) ; P1.E4 v1(67.61,54.75) ; P1.A29 v1(72.69,23) ; C37.2 v3(33.15,38.57) ; P1.C25 v1(70.15,28.08) ; P1.C24 v1(70.15,29.35) ; P1.C29 v1(70.15,24.27) P1.C28 ; P1.J5 v1(62.53,53.48) ; P1.A20 v1(72.69,34.43) ; P1.J40 v1(62.53,9.03) ; P1.D25 v1(68.88,28.08) ; P1.A12 v1(72.69,44.59) ; P1.A28 v1(72.69,24.27) ; P1.A16 v1(72.69,39.51) ; P1.A13 v1(72.69,43.32) ; P1.F39 v1(66.34,10.3) ; C546.1 v4(32.7,35.2) ; P1.A33 v1(72.69,17.92)
  BOTTOM w0.305: C616.2 C614.2 v3(27.56,9.99) ; v6(28.83,43.52) 29.15,43.2 C541.1 ; C43.2 32.84,36.9 v6(32.84,36.58) ; v6(28.83,40.98) 28.83,41.05 C3.2 ; v6(28.96,38.19) 28.73,37.96 C538.2 ; C558.2 25.21,42.7 v6(25.33,42.58) ; U8.24 9.11,58.37 U8.PAD ; v6(31.83,43.47) 32.19,43.84 C554.2 ; v6(29.34,38.19) 29.56,37.96 C550.2 ; U10.30 46.23,29.93 v3(46.48,29.68) 48.23,27.93 ; v6(26.83,42.08) 26.87,42.12 C539.2 ; C545.2 26.87,37.04 v6(26.83,37.08) ; C620.2 v3(26.61,7.9) ; U8.14 6.04,56.62 v4(5.77,56.35) 6,56.12 U8.13 ; C622.2 v3(26.61,9.04) ; C648.2 v3(24.57,8.02) ; C544.2 v6(30.67,39.9) ; C617.2 v3(27.56,12.53) ; v6(32.81,42.58) 32.83,42.57 C20.2 ; C2.2 29.33,40.91 v6(29.33,40.58) ; U10.2 48.73,27.43 48.23,27.93 ; 48.23,27.93 U10.3 ; C31.2 32.83,41.04 v6(32.87,41.08) ; U19.4 2.17,10.89 U19.PAD ; U8.12 v4(6.48,55.17) ; C532.1 28.89,35.58 v6(28.83,35.52) ; v6(30.33,43.5) 30.5,43.33 C535.1 ; C612.2 v3(27.56,13.3)
  BOTTOM w0.508: C41.1 v4(56.39,34.5) ; C61.1 v3(20.07,13.42) ; v3(23.62,56.48) 23.2,56.06 C432.1 ; v4(30.31,3.81) C317.1 C310.1 ; R436.2 R429.1 v4(49.53,51.27) ; v3(23.5,57.87) 23.41,57.78 C426.2 ; v3(46.48,29.68) 44.32,30.06 ; v3(46.48,29.68) 44.96,29.42 ; v3(46.48,29.68) 45.59,28.79 ; v3(46.48,29.68) 45.47,28.92 ; P1.G14 P1.H15 ; R1.2 v4(37.21,45.43) ; XC4.N v4(57.91,64.22) ; C664.1 7.3,15.54 v4(7.44,15.4) ; v4(50.04,60.67) 50,60.63 XC6.2 ; C566.P v4(22.23,47.9) ; 34.54,4.28 v3(34.92,4.28) ; v3(37.85,34.5) 37.97,34.38 C48.1 ; 48.33,48.67 47.31,48.67 ; 48.33,48.67 48.64,48.98 v4(48.64,49.49) ; 48.33,48.67 v4(49.66,48.67) ; 47.31,48.67 L45.1 ; 47.31,48.67 47.62,48.98 v4(47.62,49.49) ; v3(18.41,14.69) R61.1 v3(17.53,15.2) ; R41.1 v4(36.83,29.55) ; C645.1 v4(28.19,5.55) ; v4(45.85,15.58) 46.09,15.34 FL1.5 ; v4(29.59,14.69) 30.1,14.18 C313.1 ; C42.1 v3(40.32,37.11) ; FL1.3 v3(49.08,5.35) ; R76.2 16.45,54.68 17.13,54.68 v4(17.4,54.95) ; 35.56,27.01 35.56,26.12 v4(35.81,25.87) ; C46.1 v4(38.7,25.53) ; v4(16,14.57) 15.46,14.02 C657.1 ; C437.2 v3(58.93,51.14) ; C670.1 v4(3.85,6.35) ; C661.1 v3(1.02,8.22) ; C419.1 v4(35.12,20.85) ; R78.2 v4(6.48,51.14) ; C435.2 v3(18.16,54.82) ; 12.45,63.21 v3(13.34,63.21) ; R42.2 v4(39.62,24.98) ; R9.2 v4(46.48,53.55) ; C312.1 v4(29.08,4.02) ; C410.1 v4(56.01,27.52) C411.1 R413.2 ; XC12.1 v3(49.91,63.21) ; FL1.6 v4(54.66,13.37) ; C518.1 34.58,65.53 v4(33.66,64.6) ; C522.1 v4(37.47,56.73) ; C658.1 v3(5.55,11.86) ; 39.75,20.15 v4(38.61,20.15) ; C427.1 v4(20.07,63.33) ; C49.1 v4(56.77,27.14) ; C667.1 v4(3.81,15.45) ; C430.1 v4(58.93,46.19) ; v4(58.04,16.72) 58.04,17.61 ; C515.2 v4(36.23,57.4) ; C47.1 v4(54.48,32.73) ; C69.1 17.27,6.82 ; C436.2 v3(55.88,51.14) ; C66.1 v3(18.92,9.74) ; R80.2 v4(4.19,51.14) ; C315.1 v3(28.57,13.55) ; U19.PAD 3.81,12.03 ; C651.1 v3(25.95,4.95)
  BOTTOM w0.635: 18.53,19.63 TP42.1 ; TP42.1 20.59,19.63 ; TP42.1 18.53,21.69 ; TP42.1 20.59,21.69 ; 70.95,4.07 TP64.1 ; TP64.1 70.95,2.46 ; TP64.1 72.56,4.07 ; TP64.1 72.56,2.46 ; 45.17,63.11 XP2.G1 47,63.11 ; 60.74,67.23 XP1.6 ; XP1.6 62.45,67.23 ; XP1.6 62.45,65.53 ; XP1.6 60.74,65.53 ; 45.46,58.73 XP2.5 44.21,57.48
  vias: v1(3.56,23.07) v1(3.56,20.53) v1(4.45,15.96) v1(4.7,23.07) v1(5.08,20.53) v1(5.21,17.74) v1(5.59,23.96) v1(5.72,19.26) v1(6.48,24.85) v1(6.48,20.15) v1(6.99,21.8) v1(7.37,21.04) v1(7.49,25.87) v1(7.62,16.6) v1(7.75,17.61) v1(8.13,22.95) v1(8.13,21.8) v1(8.38,18.5) v1(8.64,26.88) v1(9.02,23.71) v1(9.02,19.14) v1(9.65,19.77) v1(10.03,27.14) v1(10.16,24.34) v1(11.3,27.14) v1(11.56,24.34) v1(12.83,24.34) v1(16.94,24.98) v1(16.94,24.27) v1(17.65,24.27) v1(18.36,24.98) v1(18.36,24.27) v1(34.29,2.75) v1(34.29,1.23) v1(35.56,0.72) v1(37.21,0.72) v1(37.34,2.12) v1(38.35,2.12) v1(38.35,0.72) v1(39.24,2.12) v1(39.24,0.72) v1(40.26,2.12) v1(40.39,0.72) v1(41.53,0.72) v1(43.43,0.72) v1(44.07,30.06) v1(44.7,29.42) v1(44.83,0.72) v1(45.09,32.09) v1(45.34,28.79) v1(45.72,31.46) v1(45.97,28.15) v1(46.23,0.72) v1(46.48,30.69) v1(47.24,29.93) v1(47.5,0.85) v1(47.88,31.96) v1(47.88,29.3) v1(48.39,31.33) v1(48.51,28.66) v1(49.02,30.69) v1(50.16,61.68) v1(51.69,61.68) v1(52.83,61.68) v1(54.1,43.65) v3(19.72,15.62) v3(20.13,10.18) v3(22.86,11.39) v3(24.38,12.79) v3(29.08,9.49) v3(29.08,8.85) v3(29.08,8.22) v3(29.84,9.49) v3(29.84,8.22) v3(30.73,9.49) v3(30.73,8.85) v3(30.73,8.22) v3(34.92,13.3) v3(35.69,8.47) v3(39.24,11.77) v3(44.32,31.96) v3(44.32,30.95) v3(44.32,28.54) v3(44.32,27.27) v3(46.48,31.96) v3(46.48,27.27) v3(48.64,29.68) v3(48.64,27.27) v3(50.29,54.32) v3(50.93,54.32) v3(51.56,54.32) v3(52.83,27.65) v3(56.39,55.59) v3(56.39,53.55) v3(65.66,42.63) v4(0.94,26.95) v4(0.94,25.17) v4(0.94,18.44) v4(0.94,16.66) v4(2.21,26.95) v4(2.21,25.17) v4(2.21,18.44) v4(2.21,16.66) v4(2.16,12.03) v4(2.16,11.26) v4(2.92,12.03) v4(2.92,11.26) v4(3.48,26.95) v4(3.48,25.17) v4(3.48,18.44) v4(3.48,16.66) v4(4.7,46.57) v4(4.75,26.95) v4(4.75,25.17) v4(4.75,18.44) v4(4.75,16.66) v4(4.83,31.96) v4(6.1,50.25) v4(6.6,43.65) v4(7.24,28.66) v4(10.29,28.41) v4(11.94,45.3) v4(12.32,47.97) v4(13.59,12.03) v4(14.1,59.78) v4(15.37,45.17) v4(15.62,7.45) v4(17.14,46.95) v4(17.78,16.85) v4(18.29,47.71) v4(18.29,45.3) v4(19.69,48.09) v4(20.23,3.81) v4(22.61,3.77) v4(22.73,45.43) v4(23.45,19.2) v4(23.88,43.9) v4(24.26,28.15) v4(24.38,34) v4(24.38,33.11) v4(24.38,32.22) v4(24.38,31.46) v4(25.02,27.77) v4(26.04,27.77) v4(27.05,27.77) v4(27.43,23.24) v4(28.19,27.77) v4(28.83,33.11) v4(28.83,32.22) v4(28.83,31.33) v4(28.83,30.44) v4(28.83,29.55) v4(28.83,28.66) v4(29.72,1.87) v4(32.13,1.36) v4(34.16,32.83) v4(34.42,47.2) v4(35.18,54.95) v4(36.58,62.44) v4(37.85,47.2) v4(39.92,56.01) v4(40.35,6.09) v4(41.02,60.16) v4(41.66,51.01) v4(42.67,56.6) v4(42.67,47.08) v4(42.67,25.36) v4(42.93,61.94) v4(44.45,56.6) v4(45.59,51.01) v4(46.1,40.98) v4(47.12,39.97) v4(51.51,19.34) v4(51.54,40.79) v4(51.94,60.67) v4(52.7,13.04) v4(53.47,20.53) v4(58.67,40.35) v4(58.67,28.41) v4(58.8,24.98) v4(59.31,46.7) v4(62.36,1.1) v4(62.99,4.02) v4(65.15,62.57) v4(66.67,6.06) v4(68.33,5.55) v4(68.71,1.87) v4(70.36,7.83) v4(70.48,5.55) v4(70.74,67.27) v4(73.28,6.69) v4(73.41,64.86) v4(74.42,66.76) v4(74.42,1.99) v4(75.44,64.86) v5(9.02,58.38) v5(9.02,57.87) v5(9.02,57.36) v5(9.78,58.38) v5(9.78,57.36) v5(10.54,58.38) v5(10.54,57.87) v5(10.54,57.36) v5(11.81,9.99) v5(11.81,9.36) v5(11.81,8.72) v5(12.57,9.99) v5(12.57,8.72) v5(12.76,15.71) v5(13.34,9.99) v5(13.34,8.72) v5(14.22,18.88) v5(14.22,17.99) v5(15.11,18.88) v5(15.11,17.99) v5(15.56,15.71) v5(15.62,13.68) v5(16.38,59.02) v5(16.38,13.61) v5(20.95,57.49) v5(20.95,56.98) v5(20.95,56.48) v5(21.08,3.58) v5(21.46,57.49) v5(21.46,56.48) v5(21.84,3.58) v5(21.97,56.98) v5(21.97,56.48) v5(23.24,11.9) v5(23.24,10.63) v5(23.56,17.17) v5(23.62,3.58) v5(24.51,13.17) v5(24.51,10.63) v5(24.64,3.58) v5(25.65,13.17) v5(25.65,11.9) v5(25.65,10.63) v5(30.99,57.49) v5(30.99,56.48) v5(31.5,57.49) v5(31.5,56.98) v5(31.5,56.48) v5(32,57.49) v5(32,56.98) v5(32,56.48) v5(36.25,41.06) v5(36.27,39.53) v5(36.27,38.01) v5(37.85,9.49) v5(37.85,8.85) v5(37.85,8.22) v5(38.61,9.49) v5(38.61,8.22) v5(39.5,9.49) v5(39.5,8.85) v5(39.5,8.22) v5(40.72,39.2) v5(42.9,37.04) v5(45.21,34.71) v5(46.23,10.25) v5(46.23,9.36) v5(46.23,8.6) v5(47.12,10.25) v5(47.12,9.36) v5(47.12,8.6) v5(47.88,44.16) v5(48.01,10.25) v5(48.01,9.36) v5(48.01,8.6) v5(50.16,58.89) v5(50.16,46.7) v5(50.16,46.06) v5(50.16,45.43) v5(51.44,58.89) v5(52.7,58.89) v5(59.21,12.53) v5(66.55,42.89) v5(66.55,41.62) v5(66.93,38.82) v5(67.56,47.59) v5(70.61,12.63) v6(25.33,42.08) v6(31.33,40.58) v6(31.83,36.08) v6(70.78,14.75)
SVDD12: length 10.3
  TOP w0.254: U1.N2 v6(30.83,36.58) U1.M3 U1.L3 ; v6(31.33,39.58) v6(31.33,40.08) v6(31.83,40.08) v6(31.83,40.58) ; U1.K2 v6(29.58,36.58) U1.J2 ; v6(31.83,37.08) U1.P4 ; v6(29.83,42.58) U1.J14 ; U1.P12 v6(31.83,41.83) U1.P13 ; U1.N14 v6(30.83,42.58) U1.M13 U1.L13 ; v6(31.83,39.08) v6(31.83,38.58)
  BOTTOM w0.254: C535.2 30.83,42.66 v6(30.83,42.58) ; C541.2 29.81,42.57 v6(29.83,42.58) ; v6(30.83,36.58) 30.86,36.55 C26.1 ; v6(32.33,36.08) 32.39,36.03 C546.2 ; v6(31.83,38.58) 31.84,38.57 C37.1 ; v6(31.83,37.08) 31.87,37.04 C43.1 ; C554.1 32.39,43.08 v6(32.33,43.08) ; v6(31.83,40.58) 31.84,40.6 C31.1 ; C20.1 32.12,42.12 v6(31.83,41.83) ; v6(29.58,36.58) 29.34,36.34 C532.2
  vias: v4(32,54.32) v4(32,53.17) v4(33.15,54.32) v4(33.15,53.17)
VCC: length 23
  TOP w0.508: v4(9.61,60.87) 10.29,61.56 R51.2 ; R50.2 4.83,62.06 v4(4.24,62.65) R30.1 ; v4(13.14,64.03) 12.62,63.51 R29.1 ; R327.1 24.88,64.55 25.27,64.95 v4(25.4,64.95) ; R40.1 v5(8.31,62.77) ; R52.2 v4(16.38,65.24)
  L2_GROUND w0.508: v5(8.31,62.77) 8.31,62.11 v4(7.24,61.05)
  BOTTOM w0.254: U8.25 v4(9.61,60.87) ; C58.1 6.73,61.55 v4(7.24,61.05) 7.49,60.79 7.79,60.79 8.11,60.48 U8.22
  BOTTOM w0.508: R63.1 v4(17.27,62.06) ; R68.1 v4(2.54,57.49) ; R57.2 R58.2 ; R58.2 8.76,51.14 8.51,50.89 v4(8.51,50.63) ; R58.2 R56.2 ; R77.1 v4(5.33,51.14) ; R53.1 v4(2.54,58.63) ; v4(17.4,53.94) 16.71,53.25 R55.2 ; R79.1 v4(2.16,52.03)
VDDA12: length 0.9
  TOP w0.254: v6(25.83,42.08) v6(25.83,42.58)
  BOTTOM w0.254: v6(25.83,42.58) 25.84,42.6 C558.1
  vias: v4(22.48,54.57) v4(22.48,53.81) v4(23.11,54.57) v4(23.11,53.81)
VDDA25: length 20.9
  TOP w0.254: v1(9.27,33.11) 9.14,32.98 C32.4 ; 9.53,56.17 9.53,56.18 U13.2 ; C32.2 9.27,31.96 v1(9.4,31.84) ; C32.8 6.76,31.46 6.58,31.28 6.55,31.28 v1(6.35,31.08) ; v4(6.35,46.82) 6.48,46.7 C33.2 ; v4(6.35,45.17) 6.86,45.68 C33.4 ; v4(9.4,47.71) 8.89,47.2 C33.8 ; C32.6 v1(6.35,32.47) ; U1.C8 v6(25.83,39.58) ; 9.53,55.71 9.53,55.72 ; C33.6 9.27,46.19 v4(9.4,46.06) ; U1.C7 v6(25.83,39.08)
  TOP w0.305: 9.53,55.72 9.53,55.21 9.53,55.21
  TOP w0.508: 14.1,54.82 14.22,54.82 15.11,55.71 15.11,59.65 15.49,60.03 16.89,60.03 v4(17.53,60.67)
  BOTTOM w0.254: C543.1 25.83,38.81 v6(25.83,38.58) ; v6(25.83,40.08) 25.83,39.85 C537.1
  BOTTOM w0.508: R59.1 17.14,60.29 v4(17.53,60.67) ; C549.1 v4(14.35,49.02)
  vias: v1(9.14,37.93) v1(9.27,40.73) v1(10.16,40.73) v1(10.16,37.93) v1(11.05,40.73) v1(11.05,37.93) v1(11.94,40.73) v1(11.94,37.93) v1(12.83,40.73) v1(12.83,37.93) v1(13.72,41.87) v1(13.72,40.73) v1(13.72,37.93) v1(13.72,36.66) v1(14.99,36.66) v1(15.11,41.87) v1(15.88,36.66) v1(16,41.87) v1(16.76,36.66) v1(16.89,41.87) v1(17.65,41.11) v1(17.65,40.35) v1(17.65,39.46) v1(17.65,38.57) v1(17.65,37.68) v1(17.78,41.87) v1(17.78,36.66) v1(18.67,41.87) v1(18.67,36.66) v1(19.56,41.87) v1(19.56,36.66) v1(20.32,41.87) v1(20.45,36.66) v4(9.78,41.74) v4(9.91,36.92) v4(13.34,52.41) v4(13.97,52.67) v4(13.97,51.78) v6(21.08,37.55) v6(21.08,36.79) v6(21.08,35.9) v6(21.21,43.14) v6(21.21,42.38) v6(21.21,41.49) v6(21.72,37.55) v6(21.72,36.79) v6(21.72,35.9) v6(21.84,43.14) v6(21.84,42.38) v6(21.84,41.49) v6(22.35,36.79) v6(22.35,35.9) v6(22.48,42.38) v6(22.48,41.49) v6(24.38,41.11) v6(24.38,37.55) v6(24.77,40.73) v6(24.77,37.81) v6(25.33,40.58) v6(25.33,40.08) v6(25.33,38.58) v6(25.33,38.08) v6(25.33,36.58) v6(25.83,41.58) v6(25.83,37.08) v6(26.33,43.08) v6(26.33,41.08) v6(26.33,37.58)
VDDA25_EN: length 11
  TOP w0.203: v1(12.38,60.92) 11.87,60.92 11.36,60.41 10.03,60.41 9.53,59.91 U13.7 ; Q4.PAD2 15.03,63.94 Q4.3 v1(15.62,63.21) 16.33,63.21 R52.1
  L3_SIGNAL w0.203: v1(12.38,60.92) 13.27,61.81 15.24,61.81 15.62,62.19 v1(15.62,63.21)
VDDC12: length 4.3
  TOP w0.254: v6(27.83,37.08) U1.F2 v6(27.83,36.08) ; U1.E15 v6(27.83,43.08) U1.F14 v6(27.83,42.08)
  BOTTOM w0.254: C533.1 27.62,37.29 v6(27.83,37.08) 27.79,37.04 C545.1 ; C539.1 27.79,42.12 v6(27.83,42.08) 27.62,41.88 C536.1
  vias: v4(27.3,51.78) v4(27.3,50.89) v4(27.3,49.74) v4(27.3,48.73)
VIN_12V: length 29
  TOP w0.508: DS2.A v4(53.76,6.22)
  L3_SIGNAL w0.203: v4(53.76,6.22) 53.72,6.26 53.72,7.96 52.07,9.61 52.07,13.42 53.28,14.63 v4(53.28,15.13)
  BOTTOM w0.254: v4(50.8,32.98) 50.25,32.43 U10.37
  BOTTOM w0.305: v4(42.29,32.09) 42.45,31.93 U10.23 ; U10.7 46.23,25.36 46.48,25.11 46.73,25.36 U10.6
  BOTTOM w0.508: v1(9.14,64.48) 9.14,63.97 9.02,63.84 R54.1 ; R428.1 v4(52.7,52.28) ; 40,34.5 39.75,34.76 C42.2 ; v4(51.68,16.97) FL1.2 ; C45.2 C44.2 45.72,19.84 46.47,20.59 46.47,21.02 46.48,21.03 46.48,21.36 46.48,21.37 46.48,25.11
  vias: v4(42.67,20.15) v4(43.69,20.15) v4(51.69,15.96) v4(51.82,14.95) v4(54.74,44.79)
3P3VAUX: length 1.5
  TOP w0.508: C818.2 v1(74.55,58.51)
  BOTTOM w0.254: v1(68.88,20.46) P1.D32
  vias: v1(74.17,55.84)
73_SYNC: length 3.6
  BOTTOM w0.203: U11.4 51.7,47.07 51.5,47.27 51.5,48.54 50.67,49.36 50.67,49.74 R429.2
73_VREF: length 4
  TOP w0.203: C429.2 v1(54.74,47.84)
  BOTTOM w0.203: 54.92,47.08 54.91,47.07 U11.9 ; 54.92,47.08 54.74,47.26 v1(54.74,47.84) ; 54.92,47.08 55.26,47.08 55.53,47.34 55.97,47.34 55.99,47.33 57.15,47.33 R434.2
73_VREG: length 13.3
  L10_SIGNAL w0.203: v1(55.75,44.41) 55.5,44.16 54.35,44.16 52.07,46.43 52.07,47.2 51.18,48.09 v1(50.29,48.09)
  BOTTOM w0.203: U11.11 55.76,46.07 55.91,46.21 56.6,46.21 56.63,46.19 C430.2 57.28,45.93 v1(55.75,44.41) ; v1(50.29,48.09) R425.1
AD9508_VDD: length 6.7
  TOP w0.508: R313.1 v4(43.94,3.01) ; R38.2 v4(51.18,3.52) R36.2 50.43,3.15 48.9,3.15 48.77,3.27 R39.2 ; v4(42.16,4.02) 42.16,5.93
  vias: v4(44.45,10.88) v4(49.53,12.28) v4(49.91,10.76)
